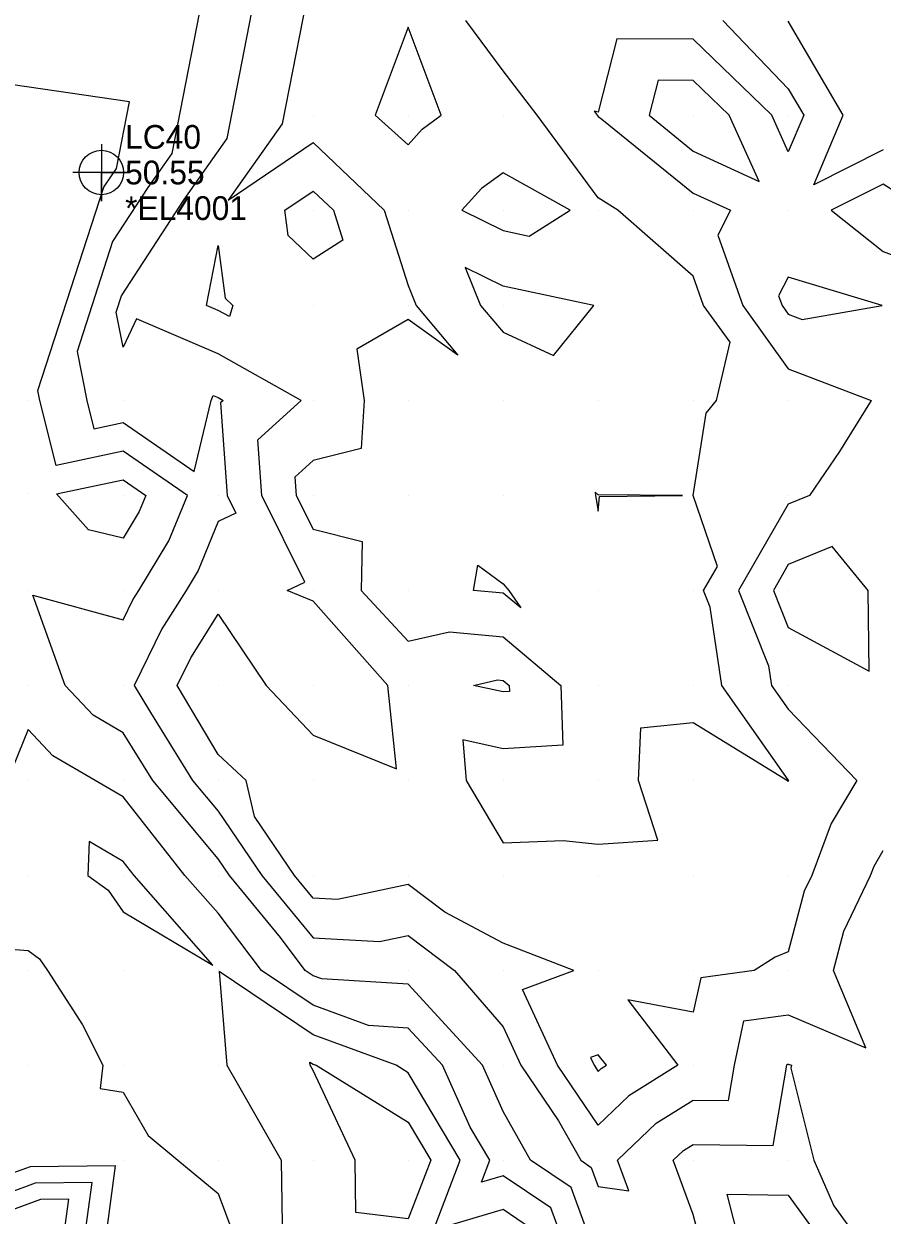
# Model space of a CAD drawing. Extents: x 2188792 to 2191981, y 386090 to 389710.
# Drawn here: x 2190119.7 to 2190210, y 387324.4 to 387449.8 of the extents above; entities that cross this region are included whole.
import ezdxf

# ---------------------------------------------------------------- set-up
doc = ezdxf.new("R2010")
doc.units = 0
for name, color, linetype in [('DTM Contours Major', 7, 'Continuous'), ('DTM Contours Minor', 7, 'Continuous'), ('Exist DTM QL2 LIDAR Elevation Point', 7, 'Continuous'), ('Exist DTM Regular Point Underwater CELL', 7, 'Continuous'), ('Exist DTM Regular Point Underwater Cogo Comment', 7, 'Continuous'), ('Exist DTM Regular Point Underwater Cogo Elevation', 7, 'Continuous'), ('Exist DTM Regular Point Underwater Cogo Number', 7, 'Continuous')]:
    doc.layers.add(name, color=color, linetype=linetype)

msp = doc.modelspace()

# ---------------------------------------------------------------- linework, layer by layer
at = {"layer": 'DTM Contours Major'}
for points in [[(2190193.24, 387450.15), (2190200.13, 387442.93), (2190201.76, 387440.15), (2190200.13, 387436.3), (2190198.38, 387440.15), (2190190.13, 387448.16), (2190182.08, 387448.2), (2190180.12, 387440.5), (2190179.69, 387440.58), (2190180.02, 387440.15), (2190180.12, 387440.01), (2190180.52, 387439.76), (2190190.13, 387431.95), (2190194.05, 387430.15), (2190192.72, 387427.55), (2190195.35, 387420.14), (2190200.13, 387413.48), (2190208.84, 387410.14), (2190205.5, 387404.77), (2190202.35, 387400.14), (2190200.13, 387399.23), (2190194.87, 387390.14), (2190198.06, 387382.21), (2190198.36, 387380.14), (2190200.13, 387377.63), (2190207.35, 387370.14), (2190204.65, 387365.61), (2190202.59, 387360.14), (2190201.8, 387358.47), (2190200.13, 387352.09), (2190198.75, 387351.51), (2190196.52, 387350.14), (2190190.91, 387349.36), (2190190.13, 387345.72), (2190183.24, 387347.02), (2190188.49, 387340.14), (2190183.33, 387336.93), (2190180.12, 387333.83), (2190175.84, 387340.14), (2190172.15, 387348.11), (2190177.54, 387350.14), (2190170.12, 387352.99), (2190163.98, 387356.28), (2190160.12, 387359.18), (2190152.67, 387357.59), (2190150.12, 387357.74), (2190148.16, 387360.14), (2190143.94, 387366.32), (2190143.07, 387370.14), (2190140.12, 387372.86), (2190135.82, 387380.14), (2190137.23, 387383.03), (2190140.12, 387387.62), (2190145.16, 387380.14), (2190150.12, 387374.9), (2190158.89, 387371.37), (2190157.99, 387380.14), (2190150.12, 387389), (2190147.39, 387390.14), (2190149.25, 387391.01), (2190144.71, 387400.14), (2190144.29, 387405.98), (2190148.86, 387410.14), (2190140.12, 387415.03), (2190131.54, 387418.73), (2190130.12, 387415.75), (2190129.4, 387419.42), (2190129.96, 387421.15), (2190136.55, 387431.3), (2190141.06, 387437.7), (2190150.12, 387484.23)], [(2190150.12, 387424.99), (2190147.48, 387427.51), (2190147.13, 387430.15), (2190150.12, 387432.18), (2190152.25, 387430.15), (2190153.26, 387427.01), (2190150.12, 387424.99)], [(2190210.13, 387432.89), (2190204.65, 387430.15), (2190210.13, 387425.82), (2190217, 387423.27), (2190214.42, 387430.15), (2190210.13, 387432.89)], [(2190166.99, 387380.14), (2190169.54, 387380.73), (2190170.12, 387380.67), (2190170.75, 387380.14), (2190170.78, 387379.49), (2190170.12, 387379.45), (2190166.99, 387380.14)], [(2190160.12, 387323.97), (2190154.63, 387324.65), (2190154.55, 387330.14), (2190150.12, 387339.58), (2190149.81, 387340.14), (2190149.78, 387340.48), (2190150.12, 387340.25), (2190150.43, 387340.14), (2190160.12, 387334.14), (2190162.51, 387330.14), (2190160.12, 387323.97)], [(2190124.02, 387323.25), (2190124.4, 387326.05), (2190121.42, 387326.01), (2190110.83, 387322.11)]]:
    msp.add_lwpolyline(points, dxfattribs=at)
at = {"layer": 'DTM Contours Minor'}
for points in [[(2190141.59, 387468.7), (2190135.24, 387436.13), (2190132.71, 387432.55), (2190129.02, 387426.86), (2190125.27, 387415.3), (2190126.29, 387410.14), (2190127.04, 387407.15), (2190130.12, 387407.81), (2190137.61, 387402.65), (2190139.37, 387410.14), (2190139.61, 387410.65), (2190140.12, 387410.43), (2190140.64, 387410.14), (2190140.37, 387409.9), (2190141.07, 387400.14), (2190142, 387398.26), (2190140.12, 387397.38), (2190138.01, 387392.25), (2190136.74, 387390.14), (2190134.18, 387386.08), (2190131.3, 387380.14), (2190132.99, 387377.27), (2190137.42, 387370.14), (2190140.12, 387366.9), (2190144.73, 387360.14), (2190150.12, 387353.56), (2190157.1, 387353.16), (2190160.12, 387353.8), (2190165, 387350.14), (2190170.12, 387344.18), (2190171.99, 387340.14), (2190175.96, 387334.3), (2190178.29, 387330.14), (2190179.39, 387329.4), (2190180.12, 387327.37), (2190183.35, 387326.92), (2190182.16, 387330.14), (2190186.21, 387334.05), (2190190.13, 387336.48), (2190193.82, 387336.44), (2190194.45, 387340.14), (2190195.46, 387344.81), (2190200.13, 387345.46), (2190208.3, 387341.97), (2190204.9, 387350.14), (2190205.98, 387354.28), (2190208.78, 387360.14), (2190209.15, 387361.12), (2190210.13, 387362.76)], [(2190150.12, 387455.94), (2190146.87, 387439.27), (2190141.19, 387431.22), (2190150.12, 387437.29), (2190157.59, 387430.15), (2190160.12, 387422.25), (2190160.98, 387420.14), (2190165.36, 387414.91), (2190160.12, 387418.67), (2190154.72, 387415.55), (2190155.48, 387410.14), (2190155.18, 387405.08), (2190150.12, 387403.8), (2190148.21, 387402.05), (2190148.35, 387400.14), (2190150.12, 387396.58), (2190155.28, 387395.3), (2190155.18, 387390.14), (2190160.12, 387384.79), (2190164.48, 387385.79), (2190170.12, 387385.26), (2190176.19, 387380.14), (2190176.41, 387373.85), (2190170.12, 387373.45), (2190165.87, 387374.39), (2190166.23, 387370.14), (2190170.12, 387363.58), (2190176.45, 387363.82), (2190180.12, 387363.42), (2190186.4, 387363.86), (2190184.37, 387370.14), (2190184.61, 387375.66), (2190190.13, 387376.22), (2190200.04, 387370.14), (2190200.13, 387370.02), (2190200.16, 387370.11), (2190200.18, 387370.14), (2190200.13, 387370.2), (2190193.13, 387380.14), (2190191.91, 387388.36), (2190191.19, 387390.14), (2190192.66, 387392.67), (2190190.13, 387400.14), (2190191.49, 387408.78), (2190192.57, 387410.14), (2190194, 387416.27), (2190191.22, 387420.14), (2190190.13, 387423.23), (2190182.18, 387430.15), (2190180.12, 387431.46), (2190173.68, 387440.15), (2190170.12, 387444.85), (2190166.2, 387450.15)], [(2190210.13, 387436.5), (2190202.82, 387432.84), (2190205.92, 387440.15), (2190200.13, 387450.05)], [(2190161.59, 387438.68), (2190163.61, 387440.15), (2190160.12, 387449.42), (2190156.65, 387440.15), (2190160.12, 387437.05), (2190161.59, 387438.68)], [(2190179.86, 387320.14), (2190177.26, 387327.27), (2190173.01, 387330.14), (2190170.12, 387335.29), (2190167.95, 387340.14), (2190160.12, 387348.67), (2190151.02, 387349.24), (2190150.12, 387349.57), (2190149.28, 387350.14), (2190146.68, 387353.58), (2190141.31, 387360.14), (2190140.12, 387361.88), (2190133.24, 387370.14), (2190130.12, 387375.16), (2190126.97, 387376.99), (2190124.02, 387380.14), (2190120.61, 387389.65), (2190130.12, 387387.05), (2190131.13, 387389.13), (2190131.77, 387390.14), (2190134.92, 387395.35), (2190136.89, 387400.14), (2190130.12, 387404.8), (2190123.07, 387403.29), (2190121.36, 387410.14), (2190121.15, 387411.18), (2190128.09, 387432.57), (2190128.88, 387433.79), (2190129.42, 387434.56), (2190130.79, 387441.56), (2190112.27, 387444.26)], [(2190197.07, 387433.2), (2190193.91, 387440.15), (2190190.13, 387443.82), (2190186.43, 387443.84), (2190185.5, 387440.15), (2190190.13, 387436.38), (2190197.07, 387433.2)], [(2190177.17, 387430.15), (2190170.12, 387434.09), (2190167.83, 387432.43), (2190165.77, 387430.15), (2190170.12, 387428.01), (2190172.84, 387427.43), (2190177.17, 387430.15)], [(2190140.12, 387419.62), (2190138.91, 387420.14), (2190140.12, 387426.44), (2190140.87, 387420.9), (2190141.66, 387420.14), (2190141.31, 387418.96), (2190140.12, 387419.62)], [(2190170.12, 387422.18), (2190166.12, 387424.14), (2190167.75, 387420.14), (2190170.12, 387417.31), (2190175.42, 387414.85), (2190179.67, 387420.14), (2190170.12, 387422.18)], [(2190210, 387420.14), (2190200.13, 387423.13), (2190199.11, 387421.16), (2190199.47, 387420.14), (2190200.13, 387419.23), (2190201.6, 387418.67), (2190210, 387420.14)], [(2190123.1, 387400.29), (2190130.12, 387401.79), (2190132.52, 387400.14), (2190131.82, 387398.44), (2190130.12, 387395.63), (2190126.49, 387396.51), (2190123.1, 387400.29)], [(2190189.01, 387400.14), (2190180.12, 387400.2), (2190179.79, 387400.48), (2190179.83, 387400.14), (2190180.12, 387398.48), (2190180.26, 387400.01), (2190189.01, 387400.14)], [(2190208.64, 387381.63), (2190208.54, 387390.14), (2190204.73, 387394.75), (2190200.13, 387392.86), (2190198.56, 387390.14), (2190200.13, 387386.22), (2190208.64, 387381.63)], [(2190170.12, 387389.85), (2190167, 387390.14), (2190167.47, 387392.8), (2190170.12, 387390.82), (2190170.73, 387390.14), (2190171.98, 387388.29), (2190170.12, 387389.85)], [(2190176.96, 387320.14), (2190175.13, 387325.14), (2190170.12, 387328.52), (2190167.83, 387327.84), (2190168.71, 387330.14), (2190166.64, 387333.62), (2190163.72, 387340.14), (2190160.12, 387344.06), (2190155.94, 387344.32), (2190150.12, 387346.47), (2190144.67, 387350.14), (2190140.12, 387356.16), (2190136.63, 387360.14), (2190130.12, 387368.41), (2190127.17, 387370.14), (2190122.71, 387372.73), (2190120.12, 387375.5), (2190117.94, 387370.14)], [(2190139.57, 387350.68), (2190131.28, 387360.14), (2190130.12, 387361.61), (2190126.56, 387363.7), (2190126.42, 387360.14), (2190128.55, 387358.57), (2190130.12, 387356.3), (2190139.57, 387350.68)], [(2190112.77, 387352.79), (2190120.12, 387352.23), (2190121.33, 387351.35), (2190122.16, 387350.14), (2190125.84, 387344.42), (2190127.97, 387340.14), (2190127.69, 387337.71), (2190130.12, 387337.32), (2190132.75, 387332.77), (2190135.88, 387330.14), (2190140.12, 387326.66), (2190142.55, 387320.14)], [(2190160.12, 387339.36), (2190158.86, 387340.14), (2190150.12, 387343.36), (2190140.24, 387350.02), (2190141.05, 387340.14), (2190142.25, 387338), (2190146.75, 387330.14), (2190146.87, 387323.39)], [(2190180.45, 387339.81), (2190180.98, 387340.14), (2190180.12, 387341.26), (2190179.31, 387340.95), (2190179.69, 387340.14), (2190180.12, 387339.49), (2190180.45, 387339.81)], [(2190173, 387323.01), (2190170.12, 387324.95), (2190162.77, 387322.78), (2190165.61, 387330.14), (2190160.12, 387339.36)], [(2190191.23, 387320.14), (2190190.13, 387324.42), (2190188.02, 387330.14), (2190189.09, 387331.17), (2190190.13, 387331.81), (2190198.55, 387331.71), (2190199.98, 387340.14), (2190200, 387340.26), (2190200.13, 387340.28), (2190200.45, 387340.14), (2190200.41, 387339.85), (2190202.81, 387330.14), (2190204.91, 387325.35), (2190208.68, 387320.14)], [(2190128.18, 387321.12), (2190129.33, 387329.57), (2190120.33, 387329.46), (2190118.6, 387328.83)], [(2190126.1, 387322.19), (2190126.87, 387327.81), (2190120.87, 387327.74), (2190114.72, 387325.47)], [(2190193.7, 387326.56), (2190200.13, 387326.47), (2190204.71, 387320.14), (2190204.19, 387316.07), (2190202.63, 387310.13), (2190200.13, 387304.83), (2190197.93, 387310.13), (2190197.06, 387313.2), (2190195.36, 387320.14), (2190193.7, 387326.56)]]:
    msp.add_lwpolyline(points, dxfattribs=at)
at = {"layer": 'Exist DTM QL2 LIDAR Elevation Point'}
for p, q in [((2190150.12, 387440.15), (2190150.12, 387440.15)), ((2190160.12, 387440.15), (2190160.12, 387440.15)), ((2190170.12, 387440.15), (2190170.12, 387440.15)), ((2190180.12, 387440.15), (2190180.12, 387440.15)), ((2190190.13, 387440.15), (2190190.13, 387440.15)), ((2190200.13, 387440.15), (2190200.13, 387440.15)), ((2190140.12, 387430.15), (2190140.12, 387430.15)), ((2190150.12, 387430.15), (2190150.12, 387430.15)), ((2190160.12, 387430.15), (2190160.12, 387430.15)), ((2190170.12, 387430.15), (2190170.12, 387430.15)), ((2190180.12, 387430.15), (2190180.12, 387430.15)), ((2190190.13, 387430.15), (2190190.13, 387430.15)), ((2190200.13, 387430.15), (2190200.13, 387430.15)), ((2190130.12, 387420.14), (2190130.12, 387420.14)), ((2190140.12, 387420.14), (2190140.12, 387420.14)), ((2190150.12, 387420.14), (2190150.12, 387420.14)), ((2190160.12, 387420.14), (2190160.12, 387420.14)), ((2190170.12, 387420.14), (2190170.12, 387420.14)), ((2190180.12, 387420.14), (2190180.12, 387420.14)), ((2190190.13, 387420.14), (2190190.13, 387420.14)), ((2190200.13, 387420.14), (2190200.13, 387420.14)), ((2190120.12, 387410.14), (2190120.12, 387410.14)), ((2190130.12, 387410.14), (2190130.12, 387410.14)), ((2190140.12, 387410.14), (2190140.12, 387410.14)), ((2190150.12, 387410.14), (2190150.12, 387410.14)), ((2190160.12, 387410.14), (2190160.12, 387410.14)), ((2190170.12, 387410.14), (2190170.12, 387410.14)), ((2190180.12, 387410.14), (2190180.12, 387410.14)), ((2190190.13, 387410.14), (2190190.13, 387410.14)), ((2190200.13, 387410.14), (2190200.13, 387410.14)), ((2190120.04, 387400.35), (2190120.04, 387400.35)), ((2190130.12, 387400.14), (2190130.12, 387400.14)), ((2190140.12, 387400.14), (2190140.12, 387400.14)), ((2190150.12, 387400.14), (2190150.12, 387400.14)), ((2190160.12, 387400.14), (2190160.12, 387400.14)), ((2190170.12, 387400.14), (2190170.12, 387400.14)), ((2190180.12, 387400.14), (2190180.12, 387400.14)), ((2190190.13, 387400.14), (2190190.13, 387400.14)), ((2190200.13, 387400.14), (2190200.13, 387400.14)), ((2190120.12, 387390.14), (2190120.12, 387390.14)), ((2190130.12, 387390.14), (2190130.12, 387390.14)), ((2190140.12, 387390.14), (2190140.12, 387390.14)), ((2190150.12, 387390.14), (2190150.12, 387390.14)), ((2190160.12, 387390.14), (2190160.12, 387390.14)), ((2190170.12, 387390.14), (2190170.12, 387390.14)), ((2190180.12, 387390.14), (2190180.12, 387390.14)), ((2190190.13, 387390.14), (2190190.13, 387390.14)), ((2190200.13, 387390.14), (2190200.13, 387390.14)), ((2190120.12, 387380.14), (2190120.12, 387380.14)), ((2190130.12, 387380.14), (2190130.12, 387380.14)), ((2190140.12, 387380.14), (2190140.12, 387380.14)), ((2190150.12, 387380.14), (2190150.12, 387380.14)), ((2190160.12, 387380.14), (2190160.12, 387380.14)), ((2190170.12, 387380.14), (2190170.12, 387380.14)), ((2190180.12, 387380.14), (2190180.12, 387380.14)), ((2190190.13, 387380.14), (2190190.13, 387380.14)), ((2190200.13, 387380.14), (2190200.13, 387380.14)), ((2190120.12, 387370.14), (2190120.12, 387370.14)), ((2190130.12, 387370.14), (2190130.12, 387370.14)), ((2190140.12, 387370.14), (2190140.12, 387370.14)), ((2190150.12, 387370.14), (2190150.12, 387370.14)), ((2190160.12, 387370.14), (2190160.12, 387370.14)), ((2190170.12, 387370.14), (2190170.12, 387370.14)), ((2190180.12, 387370.14), (2190180.12, 387370.14)), ((2190190.13, 387370.14), (2190190.13, 387370.14)), ((2190200.13, 387370.14), (2190200.13, 387370.14)), ((2190120.12, 387360.14), (2190120.12, 387360.14)), ((2190130.12, 387360.14), (2190130.12, 387360.14)), ((2190140.12, 387360.14), (2190140.12, 387360.14)), ((2190150.12, 387360.14), (2190150.12, 387360.14)), ((2190160.12, 387360.14), (2190160.12, 387360.14)), ((2190170.12, 387360.14), (2190170.12, 387360.14)), ((2190180.12, 387360.14), (2190180.12, 387360.14)), ((2190190.13, 387360.14), (2190190.13, 387360.14)), ((2190200.13, 387360.14), (2190200.13, 387360.14)), ((2190120.12, 387350.14), (2190120.12, 387350.14)), ((2190130.12, 387350.14), (2190130.12, 387350.14)), ((2190140.12, 387350.14), (2190140.12, 387350.14)), ((2190150.12, 387350.14), (2190150.12, 387350.14)), ((2190160.12, 387350.14), (2190160.12, 387350.14)), ((2190170.12, 387350.14), (2190170.12, 387350.14)), ((2190180.12, 387350.14), (2190180.12, 387350.14)), ((2190190.13, 387350.14), (2190190.13, 387350.14)), ((2190200.13, 387350.14), (2190200.13, 387350.14)), ((2190120.12, 387340.14), (2190120.12, 387340.14)), ((2190130.12, 387340.14), (2190130.12, 387340.14)), ((2190140.12, 387340.14), (2190140.12, 387340.14)), ((2190150.12, 387340.14), (2190150.12, 387340.14)), ((2190160.12, 387340.14), (2190160.12, 387340.14)), ((2190170.12, 387340.14), (2190170.12, 387340.14)), ((2190180.12, 387340.14), (2190180.12, 387340.14)), ((2190190.13, 387340.14), (2190190.13, 387340.14)), ((2190200.13, 387340.14), (2190200.13, 387340.14)), ((2190120.12, 387330.14), (2190120.12, 387330.14)), ((2190130.12, 387330.14), (2190130.12, 387330.14)), ((2190140.12, 387330.14), (2190140.12, 387330.14)), ((2190150.12, 387330.14), (2190150.12, 387330.14)), ((2190160.12, 387330.14), (2190160.12, 387330.14)), ((2190170.12, 387330.14), (2190170.12, 387330.14)), ((2190180.12, 387330.14), (2190180.12, 387330.14)), ((2190190.13, 387330.14), (2190190.13, 387330.14)), ((2190200.13, 387330.14), (2190200.13, 387330.14))]:
    msp.add_line(p, q, dxfattribs=at)
at = {"layer": 'Exist DTM Regular Point Underwater CELL'}
msp.add_lwpolyline([(2190127.83, 387437.13), (2190127.83, 387431.13), (2190127.83, 387434.13), (2190130.83, 387434.13), (2190124.83, 387434.13)], dxfattribs=at)
msp.add_circle((2190127.83, 387434.13), 2.34, dxfattribs=at)

# ---------------------------------------------------------------- texts
at = {"layer": 'Exist DTM Regular Point Underwater Cogo Comment'}
msp.add_text('*EL4001', height=2.5, dxfattribs=at).set_placement((2190130.33, 387429.13))
at = {"layer": 'Exist DTM Regular Point Underwater Cogo Elevation'}
msp.add_text('50.55', height=2.5, dxfattribs=at).set_placement((2190130.33, 387432.88))
at = {"layer": 'Exist DTM Regular Point Underwater Cogo Number'}
msp.add_text('LC40', height=2.5, dxfattribs=at).set_placement((2190130.33, 387436.63))

doc.saveas('drawing.dxf')
